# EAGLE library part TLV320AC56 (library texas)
VOICE BAND AUDIO PROCESSOR
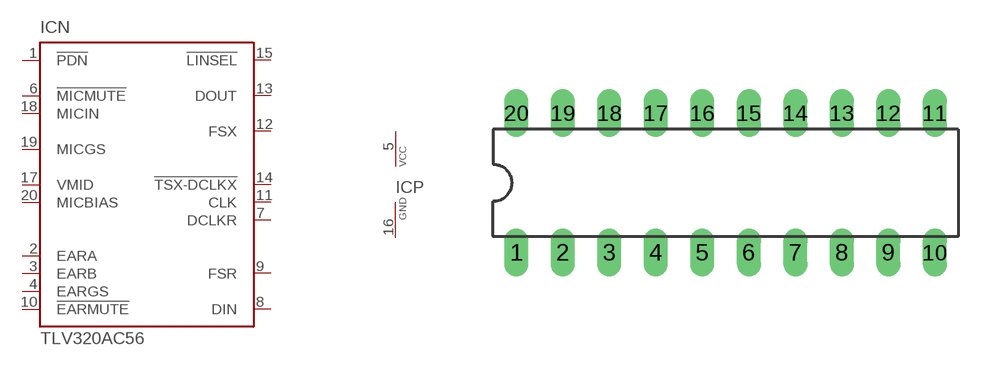
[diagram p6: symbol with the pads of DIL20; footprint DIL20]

Designator prefix IC; gates N=TLV320AC P=VCCGND

## TLV320AC56 (OC_FARNELL: unknown; OC_NEWARK: unknown)  [DIL20]
1  N:!PDN  in
2  N:EARA  out
3  N:EARB  out
4  N:EARGS  in
5  P:VCC  pwr
6  N:!MICMUTE  in
7  N:DCLKR  in
8  N:DIN  in
9  N:FSR  in
10  N:!EARMUTE  in
11  N:CLK  in
12  N:FSX  in
13  N:DOUT  out
14  N:!TSX-DCLKX
15  N:!LINSEL  in
16  P:GND  pwr
17  N:VMID  out
18  N:MICIN  in
19  N:MICGS  out
20  N:MICBIAS  out

## Footprint DIL20 (pad centres in mm)
Dual In Line Package
drill 0.813 long: 1 -11.43,-3.81; 2 -8.89,-3.81; 3 -6.35,-3.81; 4 -3.81,-3.81; 5 -1.27,-3.81; 6 1.27,-3.81; 7 3.81,-3.81; 8 6.35,-3.81; 9 8.89,-3.81; 10 11.43,-3.81; 11 11.43,3.81; 12 8.89,3.81; 13 6.35,3.81; 14 3.81,3.81; 15 1.27,3.81; 16 -1.27,3.81; 17 -3.81,3.81; 18 -6.35,3.81; 19 -8.89,3.81; 20 -11.43,3.81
